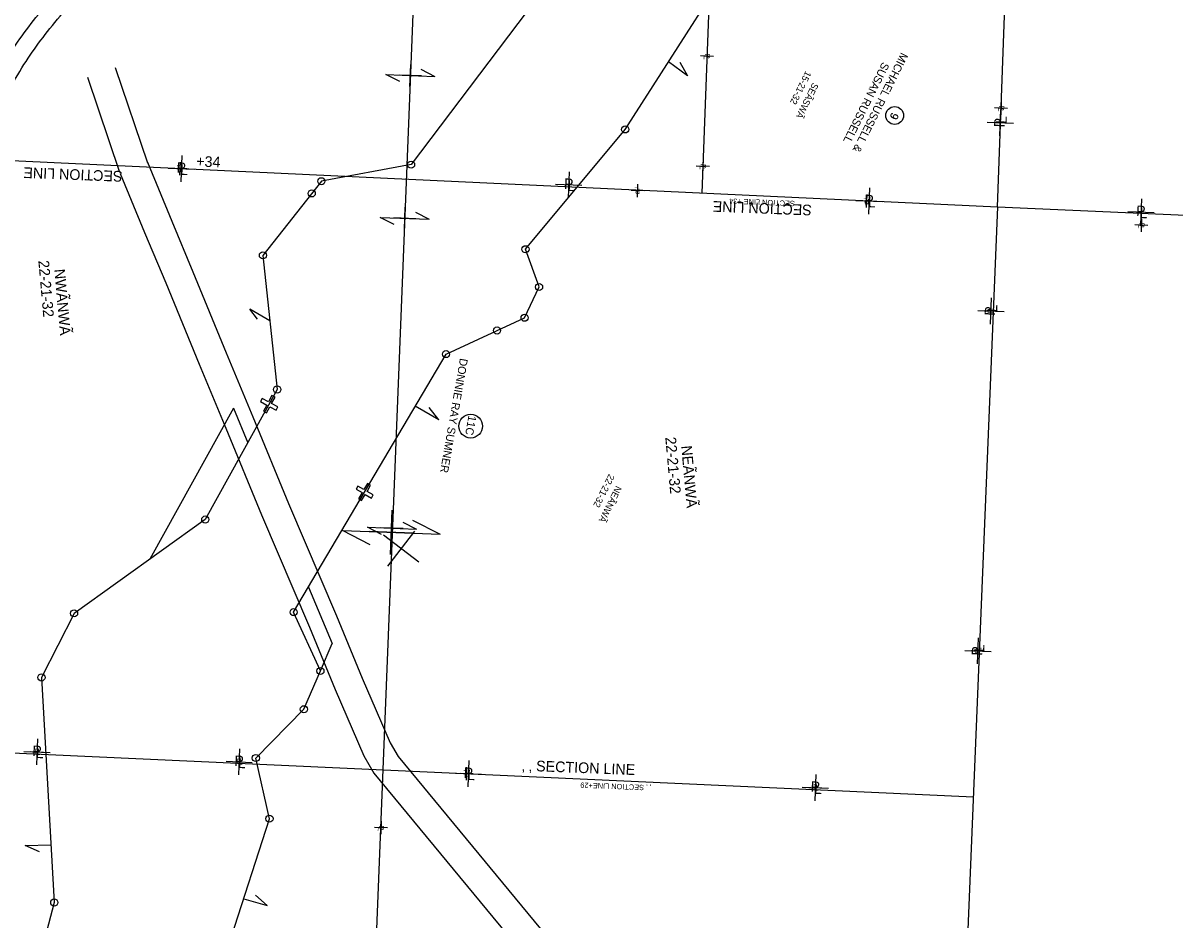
# Model space of a CAD drawing. Extents: x 2814293 to 2835768, y 121185 to 156337.
# Drawn here: x 2821316 to 2823907, y 134634 to 136651 of the extents above; entities that cross this region are included whole.
import ezdxf

# ---------------------------------------------------------------- set-up
doc = ezdxf.new("R2010")
doc.units = 0
for name, color, linetype in [('Default', 7, 'Continuous'), ('Photo-Retaining wall', 7, 'Continuous'), ('Roadway-Alignment notes', 7, 'Continuous'), ('Roadway-Ditches', 7, 'Continuous'), ('Roadway-Edge of pavement', 7, 'Continuous'), ('Roadway-Edge of shoulder', 7, 'Continuous'), ('Roadway-Entrances', 7, 'Continuous'), ('Roadway-Existing Easement', 7, 'Continuous'), ('Roadway-New rw', 7, 'Continuous'), ('Roadway-Permanent easement', 7, 'Continuous'), ('Roadway-Safety', 7, 'Continuous'), ('Roadway-Walls', 7, 'Continuous'), ('Scratch-2', 7, 'Continuous'), ('Scratch-5', 7, 'Continuous'), ('Text-New rw label', 7, 'Continuous'), ('Traffic_Control-Traffic barriers', 7, 'Continuous')]:
    doc.layers.add(name, color=color, linetype=linetype)

msp = doc.modelspace()

# ---------------------------------------------------------------- linework, layer by layer
at = {"layer": 'Default'}
for p, q in [((2822206.9, 135438.6), (2822127.5, 135499.4)), ((2822136.8, 135429.3), (2822197.6, 135508.7))]:
    msp.add_line(p, q, dxfattribs=at)
at = {"layer": 'Roadway-Ditches'}
for centre, radius in [((2823276.7, 136443), 20), ((2822323.2, 135744.5), 26.7)]:
    msp.add_circle(centre, radius, dxfattribs=at)
at = {"layer": 'Roadway-Edge of pavement'}
for p, q in [((2822186.6, 136508), (2822188.5, 136558)), ((2822132.6, 136535.1), (2822242.5, 136530.8)), ((2822163.7, 136519.1), (2822132.6, 136535.1)), ((2822212.5, 136532), (2822162.6, 136533.9)), ((2822187.6, 136533), (2822187.6, 136533)), ((2822211.4, 136546.9), (2822242.5, 136530.8)), ((2822174, 136186.7), (2822175.9, 136236.7)), ((2822198.8, 136225.6), (2822229.9, 136209.6)), ((2822120, 136213.8), (2822229.9, 136209.6)), ((2822151.1, 136197.8), (2822120, 136213.8)), ((2822199.9, 136210.7), (2822150, 136212.7)), ((2822175, 136211.7), (2822175, 136211.7)), ((2822145.5, 135490), (2822147.4, 135540)), ((2822170.3, 135528.9), (2822201.4, 135512.9)), ((2822091.5, 135517.1), (2822201.4, 135512.9)), ((2822122.6, 135501.1), (2822091.5, 135517.1)), ((2822171.4, 135514), (2822121.5, 135516)), ((2822146.4, 135515), (2822146.4, 135515))]:
    msp.add_line(p, q, dxfattribs=at)
at = {"layer": 'Roadway-Edge of shoulder'}
for p, q in [((2823513.5, 136397.6), (2823515.6, 136456.4)), ((2823485.1, 136428.1), (2823544, 136426)), ((2821673.6, 136352.9), (2821671.4, 136294)), ((2821643.1, 136324.6), (2821701.9, 136322.3)), ((2822544.9, 136316.7), (2822542.6, 136257.8)), ((2822514.3, 136288.4), (2822573.2, 136286.1)), ((2823220.3, 136280), (2823218, 136221.2)), ((2823189.7, 136251.7), (2823248.6, 136249.5)), ((2823831.7, 136255.8), (2823829.4, 136196.9)), ((2823801.1, 136227.5), (2823860, 136225.2)), ((2823492.2, 135974), (2823494.4, 136032.9)), ((2823463.9, 136004.6), (2823522.7, 136002.4)), ((2823463, 135209.7), (2823465.3, 135268.6)), ((2823434.7, 135240.3), (2823493.6, 135238)), ((2821349.1, 135041.5), (2821346.8, 134982.6)), ((2821318.5, 135013.2), (2821377.4, 135010.9)), ((2821803.5, 135019.1), (2821801.3, 134960.2)), ((2821773, 134990.8), (2821831.8, 134988.5)), ((2822319.3, 134992.3), (2822317, 134933.4)), ((2822288.7, 134964), (2822347.6, 134961.7)), ((2823099.5, 134961.1), (2823097.2, 134902.3)), ((2823068.9, 134932.8), (2823127.8, 134930.6))]:
    msp.add_line(p, q, dxfattribs=at)
at = {"layer": 'Roadway-Entrances'}
for p, q in [((2823507.8, 136237.3), (2823605.3, 138881.7)), ((2822231.2, 137625.3), (2822073.3, 133645.3)), ((2822810.6, 136532.4), (2822768, 136563.6)), ((2822793.7, 136563.1), (2822810.6, 136532.4)), ((2821534.5, 136314.7), (2821461.9, 136528.7)), ((2821597, 136335.9), (2821524.4, 136549.9)), ((2820848.6, 136362.6), (2823507.8, 136237.3)), ((2823507.8, 136237.3), (2823399.5, 133588.1)), ((2823507.8, 136237.3), (2826146.1, 136120.3)), ((2821871.6, 135981.2), (2821826.8, 136007.3)), ((2821844, 135985.4), (2821826.8, 136007.3)), ((2822251.6, 135758.7), (2822198.7, 135789.6)), ((2822251.6, 135758.7), (2822230, 135786.3)), ((2820797.9, 135032.5), (2823453.8, 134911.2)), ((2821321.5, 134801.8), (2821379.2, 134803)), ((2821353.4, 134787.6), (2821321.5, 134801.8)), ((2821839.1, 134689.8), (2821865.5, 134666.9)), ((2821812.7, 134681.9), (2821865.5, 134666.9))]:
    msp.add_line(p, q, dxfattribs=at)
at = {"layer": 'Roadway-Existing Easement'}
for points in [[(2821596.3, 136337.9), (2821650.9, 136205.5), (2821698.3, 136091.7), (2821773.4, 135909.5), (2821833.5, 135765.2), (2821913.4, 135570.6), (2822021.6, 135317.9), (2822079.5, 135177.9), (2822142.3, 135032.7), (2822160.1, 135001.6), (2822561.8, 134515.3)], [(2821535.2, 136312.7), (2821589.9, 136180.2), (2821637.3, 136066.4), (2821712.4, 135884.2), (2821772.5, 135739.9), (2821852.5, 135545.1), (2821960.7, 135292.3), (2822018.7, 135152.2), (2822083.2, 135003.1), (2822105.7, 134963.9), (2822508.4, 134476.2)]]:
    msp.add_lwpolyline(points, dxfattribs=at)
at = {"layer": 'Roadway-New rw'}
for p, q in [((2822757.7, 137084.1), (2822189.2, 136332.5)), ((2822189.2, 136332.5), (2821987.4, 136295.2)), ((2821987.4, 136295.2), (2821856, 136128.5)), ((2822477, 136057.4), (2822446.4, 136142.2)), ((2821856, 136128.5), (2821888, 135826.9)), ((2822444.4, 135988.2), (2822477, 136057.4)), ((2822267.7, 135906.5), (2822444.4, 135988.2)), ((2821925, 135326.4), (2822267.7, 135906.5)), ((2821888, 135826.9), (2821726.2, 135534.5)), ((2821726.2, 135534.5), (2821431.2, 135323.5)), ((2821431.2, 135323.5), (2821357.9, 135179.4)), ((2821985.2, 135194), (2821925, 135326.4)), ((2821948, 135107.9), (2821985.2, 135194)), ((2821357.9, 135179.4), (2821386.6, 134673.4)), ((2821840, 134998.2), (2821948, 135107.9)), ((2821870.7, 134861.8), (2821840, 134998.2)), ((2821784.7, 134594.9), (2821870.7, 134861.8)), ((2821386.6, 134673.4), (2821299.8, 134343.2))]:
    msp.add_line(p, q, dxfattribs=at)
for points in [[(2822670.7, 136411.7), (2822990.8, 136911.6)], [(2822446.4, 136142.2), (2822670.7, 136411.7)]]:
    msp.add_lwpolyline(points, dxfattribs=at)
for points in [[(2821854.4, 135806.7), (2821850.6, 135799.7), (2821864.7, 135792), (2821857, 135778), (2821864.1, 135774.2), (2821871.7, 135788.2), (2821885.8, 135780.6), (2821889.6, 135787.6), (2821875.5, 135795.3), (2821883.2, 135809.3), (2821876.1, 135813.1), (2821868.5, 135799.1), (2821854.4, 135806.7)], [(2822069.3, 135609.9), (2822065.3, 135603), (2822079.1, 135595), (2822071.1, 135581.1), (2822078, 135577.1), (2822086, 135590.9), (2822099.8, 135582.9), (2822103.9, 135589.8), (2822090.1, 135597.8), (2822098.1, 135611.6), (2822091.2, 135615.7), (2822083.1, 135601.9), (2822069.3, 135609.9)]]:
    msp.add_lwpolyline(points, close=True, dxfattribs=at)
at = {"layer": 'Roadway-Permanent easement'}
for p, q in [((2821789.5, 135785.1), (2821601.4, 135445.2)), ((2821789.5, 135785.1), (2821821.7, 135707.1)), ((2821958.1, 135382.4), (2822011.7, 135255.5)), ((2821985.2, 135194), (2822011.7, 135255.5))]:
    msp.add_line(p, q, dxfattribs=at)
at = {"layer": 'Roadway-Walls'}
for p, q in [((2822855, 136591.2), (2822854, 136561.7)), ((2822869.2, 136575.9), (2822839.8, 136577)), ((2823530.8, 136459), (2823501.4, 136460)), ((2823516.6, 136474.2), (2823515.6, 136444.8)), ((2821684.7, 136323), (2821655.2, 136324.1)), ((2821669.4, 136308.9), (2821670.5, 136338.3)), ((2822860, 136328.4), (2822830.6, 136329.4)), ((2822845.8, 136343.6), (2822844.8, 136314.2)), ((2822713.3, 136273.3), (2822683.9, 136274.5)), ((2822698, 136259.2), (2822699.2, 136288.6)), ((2823228.8, 136250), (2823199.4, 136251.2)), ((2823213.5, 136235.9), (2823214.7, 136265.3)), ((2823846.4, 136195.8), (2823817, 136196.9)), ((2823832.2, 136211.1), (2823831.2, 136181.6)), ((2823492.8, 135988.8), (2823493.8, 136018.2)), ((2823478.6, 136004), (2823508, 136003)), ((2823449.5, 135239.7), (2823478.9, 135238.6)), ((2823463.7, 135224.4), (2823464.7, 135253.9)), ((2821348.4, 135026.8), (2821347.4, 134997.3)), ((2821333.2, 135012.6), (2821362.6, 135011.6)), ((2821802.9, 135004.4), (2821801.9, 134974.9)), ((2821787.7, 134990.2), (2821817.1, 134989.1)), ((2822313.7, 134948.5), (2822314.8, 134977.9)), ((2822329, 134962.6), (2822299.5, 134963.7)), ((2823083.7, 134932.2), (2823113.1, 134931.2)), ((2823098.9, 134946.4), (2823097.9, 134917)), ((2822122, 134856.2), (2822120.9, 134826.8)), ((2822136.2, 134841), (2822106.7, 134842))]:
    msp.add_line(p, q, dxfattribs=at)
at = {"layer": 'Scratch-2'}
for p, q in [((2822142.9, 135455.7), (2822146.8, 135555.6)), ((2822192.5, 135533.4), (2822254.8, 135501.4)), ((2822034.9, 135509.9), (2822254.8, 135501.4)), ((2822097.2, 135477.9), (2822034.9, 135509.9)), ((2822194.8, 135503.7), (2822094.9, 135507.6)), ((2822144.8, 135505.6), (2822144.8, 135505.6))]:
    msp.add_line(p, q, dxfattribs=at)
at = {"layer": 'Text-New rw label'}
for centre in [(2822670.7, 136411.7), (2822189.2, 136332.5), (2821987.4, 136295.2), (2821965.8, 136267.8), (2822446.4, 136142.2), (2821856, 136128.5), (2822477, 136057.4), (2822444.4, 135988.2), (2822382.4, 135959.5), (2822267.7, 135906.5), (2821888, 135826.9), (2821726.2, 135534.5), (2821431.2, 135323.5), (2821925, 135326.4), (2821357.9, 135179.4), (2821985.2, 135194), (2821948, 135107.9), (2821840, 134998.2), (2821870.7, 134861.8), (2821386.6, 134673.4)]:
    msp.add_circle(centre, 8, dxfattribs=at)
at = {"layer": 'Traffic_Control-Traffic barriers'}
msp.add_line((2822892.3, 137578.2), (2822843.3, 136268.6), dxfattribs=at)
for points in [[(2820421.9, 132323.7), (2820430.3, 132339.5), (2820446.6, 132365.4), (2820477.5, 132409.8), (2820521.7, 132462.2), (2820581.9, 132544.8), (2820633.7, 132622.6), (2820678.7, 132698.5), (2820711.5, 132765.4), (2820823.8, 132974.3), (2820869.5, 133062.1), (2820906.1, 133146.6), (2820945.5, 133258.7), (2820956.4, 133356.9), (2820952.7, 133425), (2820927.9, 133503.2), (2820893.9, 133557.3), (2820809, 133702.5), (2820771.2, 133774.3), (2820745.5, 133846.6), (2820736.3, 133904.7), (2820741, 133953.4), (2820747.2, 134000.7), (2820776.6, 134101.6), (2820833.7, 134304.6), (2820904.5, 134550.3), (2820921.6, 134614.4), (2820930.5, 134682.7), (2820930.5, 134758), (2820923.8, 134863.3), (2820917.2, 134986), (2820914.2, 135053.6), (2820915.6, 135096.1), (2820930, 135192), (2820948.1, 135310.8), (2820956, 135344.7), (2820980.6, 135392.4), (2821001.2, 135416.1), (2821028.4, 135446.7), (2821056.8, 135477.7), (2821080.7, 135513.2), (2821109.6, 135587.8), (2821118.7, 135642.2), (2821136.4, 135738.5), (2821159.1, 135874.6), (2821198.2, 136048.3), (2821218.1, 136218.9), (2821227.9, 136304.7), (2821244.8, 136389.4), (2821276, 136485.3), (2821314.1, 136552.1), (2821350.9, 136605.8), (2821391.6, 136657.6), (2821445.7, 136719.4), (2821474.7, 136755.9), (2821500.8, 136798.9), (2821531.8, 136855.4), (2821562.3, 136913.6), (2821611.3, 136995.1), (2821650.2, 137057.9), (2821673.5, 137084.5), (2821709.9, 137111.3), (2821757.5, 137132.5), (2821832.5, 137158.2), (2821931.7, 137192.9), (2821982.6, 137216.4), (2822021.4, 137239.3), (2822062.8, 137269.2), (2822096.8, 137305.8), (2822172, 137398.1), (2822219.2, 137461.1), (2822236.1, 137494), (2822253.7, 137552.5), (2822267, 137602), (2822284.6, 137644.3), (2822301.1, 137678.7), (2822325.1, 137711.8), (2822343.7, 137737.3), (2822366.9, 137773.8), (2822421.5, 137879), (2822464.2, 137966.1), (2822481.4, 138016.2), (2822492.6, 138043.8), (2822505.3, 138098.1), (2822507.9, 138141.9), (2822510.7, 138203.4), (2822514.5, 138251), (2822522.5, 138286.8), (2822534.9, 138334.4), (2822594.9, 138475.5), (2822624.6, 138559.6), (2822642.4, 138629.9), (2822654.8, 138749.4), (2822658.9, 138787.6)], [(2820745, 134137.3), (2820759.2, 134187.4), (2820796.5, 134319.8), (2820866, 134561), (2820882.3, 134622.2), (2820890.5, 134685.3), (2820890.5, 134756.7), (2820883.9, 134860.9), (2820877.2, 134984), (2820874.1, 135053.3), (2820875.7, 135099.8), (2820890.4, 135198), (2820908.8, 135318.4), (2820918.2, 135358.7), (2820947.2, 135415), (2820971.2, 135442.6), (2820998.7, 135473.5), (2821025.3, 135502.5), (2821045.1, 135531.8), (2821070.8, 135598.4), (2821079.3, 135649.1), (2821097, 135745.4), (2821119.8, 135882.3), (2821158.7, 136055), (2821178.4, 136223.5), (2821188.3, 136310.9), (2821206, 136399.5), (2821239.2, 136501.5), (2821280.2, 136573.3), (2821318.6, 136629.4), (2821360.8, 136683.1), (2821415, 136745), (2821441.8, 136778.8), (2821466.2, 136818.9), (2821496.5, 136874.2), (2821527.4, 136933.2), (2821577.1, 137015.9), (2821617.9, 137081.8), (2821646.4, 137114.1), (2821689.7, 137146.1), (2821742.9, 137169.7), (2821819.5, 137196), (2821916.7, 137230), (2821964, 137251.9), (2821999.5, 137272.8), (2822036.2, 137299.3), (2822066.7, 137332.1), (2822140.5, 137422.7), (2822185.2, 137482.3), (2822198.9, 137509), (2822215.2, 137563.4), (2822229.1, 137614.9), (2822248, 137660.6), (2822266.7, 137699.3), (2822292.7, 137735.3), (2822310.6, 137759.8), (2822332.2, 137793.7), (2822385.8, 137897), (2822427.2, 137981.4), (2822444, 138030.2), (2822454.4, 138055.9), (2822465.5, 138103.9), (2822468, 138144.1), (2822470.8, 138205.9), (2822474.8, 138257), (2822483.6, 138296.3), (2822497, 138347.3), (2822557.6, 138490), (2822586.2, 138571.2), (2822602.9, 138636.9), (2822615, 138753.6), (2822619.1, 138791.9)]]:
    msp.add_open_spline(points, degree=3, dxfattribs=at)

# ---------------------------------------------------------------- texts
at = {"layer": 'Photo-Retaining wall'}
for s, p in [('15-21-32', (2823076.7, 136544.4)), ('SEÃSWÃ', (2823092.6, 136518)), ('22-21-32', (2822634.2, 135638.2)), ('NEÃNWÃ', (2822650.1, 135611.8))]:
    msp.add_text(s, height=15, rotation=243.5041, dxfattribs=at).set_placement(p)
at = {"layer": 'Roadway-Alignment notes'}
for s, p in [('22-21-32', (2821350.8, 136116.3)), ('NWÃNWÃ', (2821386.7, 136097)), ('22-21-32', (2822760.8, 135719.2)), ('NEÃNWÃ', (2822796.6, 135699.9))]:
    msp.add_text(s, height=24, rotation=275.0693, dxfattribs=at).set_placement(p)
at = {"layer": 'Roadway-Ditches'}
for s, rotation, p in [('MICHAEL RUSSELL &', 243.5041, (2823291.3, 136585.8)), ('SUSAN RUSSELL', 243.5041, (2823249.3, 136564.5)), ('9', 248.849, (2823269.8, 136450.5)), ('9', 243.5041, (2823271, 136451.7)), ('DONNIE RAY SUMNER', 260.038, (2822299.3, 135898)), ('11C', 260.038, (2822318.4, 135769.3))]:
    msp.add_text(s, height=18, rotation=rotation, dxfattribs=at).set_placement(p)
at = {"layer": 'Roadway-Edge of shoulder'}
for s, rotation, p in [('P', 87.9775, (2823523.8, 136416)), ('L', 87.9775, (2823528.4, 136423.8)), ('P', 357.7804, (2821661.4, 136314.3)), ('L', 357.7804, (2821669.3, 136309.6)), ('P', 357.7804, (2822532.7, 136278.1)), ('L', 357.7804, (2822540.5, 136273.5)), ('P', 357.7804, (2823208.1, 136241.4)), ('L', 357.7804, (2823216, 136236.8)), ('P', 357.7804, (2823819.5, 136217.1)), ('L', 357.7804, (2823827.3, 136212.5)), ('P', 87.7804, (2823502.5, 135992.4)), ('L', 87.7804, (2823507.1, 136000.3)), ('P', 87.7804, (2823473.4, 135228.1)), ('L', 87.7804, (2823478, 135235.9)), ('P', 357.7804, (2821336.9, 135002.9)), ('L', 357.7804, (2821344.7, 134998.3)), ('P', 357.7804, (2821791.4, 134980.4)), ('L', 357.7804, (2821799.2, 134975.8)), ('P', 357.7804, (2822307.1, 134953.6)), ('L', 357.7804, (2822315, 134949)), ('P', 357.7804, (2823087.3, 134922.5)), ('L', 357.7804, (2823095.2, 134917.9))]:
    msp.add_text(s, height=23.6, rotation=rotation, dxfattribs=at).set_placement(p)
at = {"layer": 'Roadway-Safety'}
for s, p in [('SECTION LINE +34', (2823052.5, 136251)), ('‚ ‚ SECTION LINE+29', (2822729.8, 134937.2))]:
    msp.add_text(s, height=12, rotation=177.7804, dxfattribs=at).set_placement(p)
at = {"layer": 'Roadway-Walls'}
for s, rotation, p in [('P', 267.9775, (2822849.9, 136582)), ('L', 267.9775, (2822847.6, 136578)), ('L', 267.9775, (2823509.2, 136461.1)), ('P', 267.9775, (2823511.5, 136465)), ('L', 177.7804, (2821671.5, 136330.5)), ('P', 177.7804, (2821675.5, 136328.2)), ('L', 267.9775, (2822838.4, 136330.5)), ('P', 267.9775, (2822840.7, 136334.4)), ('L', 177.7804, (2822700.2, 136280.8)), ('P', 177.7804, (2822704.1, 136278.5)), ('L', 177.7804, (2823215.7, 136257.5)), ('P', 177.7804, (2823219.6, 136255.2)), ('L', 267.9775, (2823824.8, 136197.9)), ('P', 267.9775, (2823827.1, 136201.9)), ('L', 87.9775, (2823500.2, 136001.9)), ('P', 87.9775, (2823497.9, 135998)), ('P', 87.9775, (2823468.8, 135233.6)), ('L', 87.9775, (2823471.1, 135237.6)), ('P', 357.9775, (2821342.4, 135007.4)), ('L', 357.9775, (2821346.3, 135005.2)), ('P', 357.9775, (2821796.9, 134985)), ('L', 357.9775, (2821800.8, 134982.7)), ('L', 177.7804, (2822315.9, 134970.1)), ('P', 177.7804, (2822319.8, 134967.8)), ('P', 357.9775, (2823092.9, 134927.1)), ('L', 357.9775, (2823096.8, 134924.8)), ('P', 267.9775, (2822116.8, 134847)), ('L', 267.9775, (2822114.6, 134843.1))]:
    msp.add_text(s, height=11.8, rotation=rotation, dxfattribs=at).set_placement(p)
at = {"layer": 'Scratch-5'}
for s, rotation, p in [('+34', 357.2569, (2821705.5, 136328.6)), ('SECTION LINE', 177.7804, (2821540.5, 136318)), ('SECTION LINE', 177.7804, (2823090.8, 136242.1)), ('‚ ‚ SECTION LINE', 357.7804, (2822437.9, 134969.8))]:
    msp.add_text(s, height=24, rotation=rotation, dxfattribs=at).set_placement(p)

doc.saveas('drawing.dxf')
